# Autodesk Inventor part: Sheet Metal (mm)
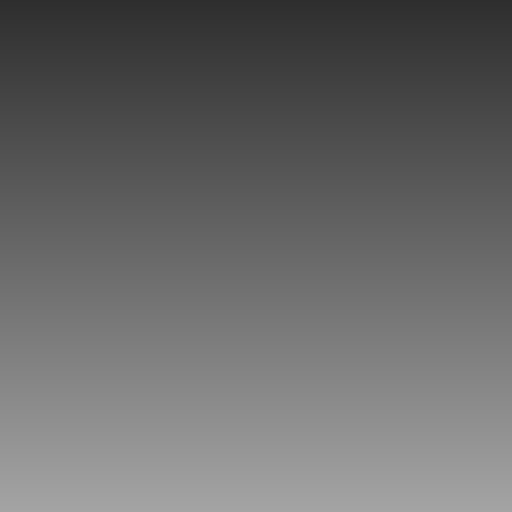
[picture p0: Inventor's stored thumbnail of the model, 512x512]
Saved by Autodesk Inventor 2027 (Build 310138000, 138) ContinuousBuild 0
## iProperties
Shininess: 64.0
Length Units: 11269
Angle Units: 11279
Time Units: 11290
Mass Units: 11283
Length Display Precision: 3
Angle Display Precision: 2
Compacted: True
Part Number: Sheet Metal (mm)
Document SubType Name: Sheet Metal
Created: 2002-07
Material: Generic
Density: 1 g/cm^3
Sheet Metal Rule: Default_mm
Appearance: Default
Density: 0.0
Volumn: 0.0
Area: 0.0
PropertySet Name: Model Information
Control State: 0
Master: False
Checked Out: False
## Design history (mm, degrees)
other parameters: "Thickness" = 0.5, "BendRadius" = 0.5 (= Thickness), "BendReliefWidth" = 0.5 (= Thickness), "BendReliefDepth" = 0.25 (= 0.5 x Thickness), "CornerReliefSize" = 2 (= 4 x Thickness), "SeamGap" = 0.01, "MinimumRemnant" = 1 (= 2 x Thickness), "TransitionRadius" = 0.5 (= BendRadius), "JacobiRadiusSize" = 0.5 (= BendRadius), "GapSize" = 0.5 (= Thickness)
